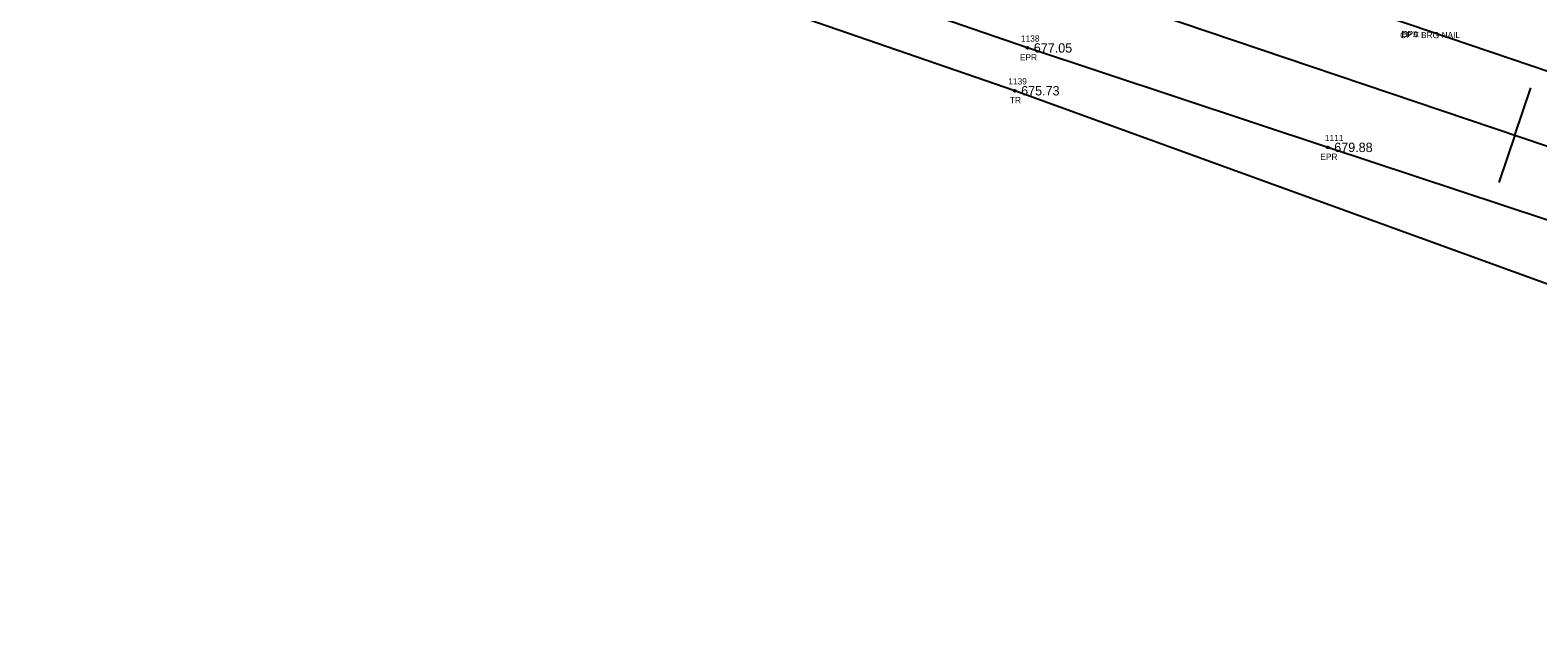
# Model space of a CAD drawing. Extents: x 1655137 to 1657928, y 1003994 to 1005407.
# Drawn here: x 1656606.1 to 1656847.1, y 1004388.9 to 1004485.2 of the extents above; entities that cross this region are included whole.
import ezdxf

# ---------------------------------------------------------------- set-up
doc = ezdxf.new("R2010")
doc.units = 0
for name, color, linetype in [('RD_EX_Driveway_txCode', 7, 'Continuous'), ('RD_EX_Road', 7, 'Continuous'), ('RD_EX_Road_txCode', 7, 'Continuous'), ('RD_EX_TX_Road_ELEV', 7, 'Continuous'), ('RD_EX_TX_VEG_ELEV', 7, 'Continuous'), ('RD_EX_VEG', 7, 'Continuous'), ('RD_EX_VEG_txCode', 7, 'Continuous'), ('RD_HC_Cl', 7, 'Continuous'), ('RD_HC_Data_Tic', 7, 'Continuous'), ('RD_HC_Survey_txCode', 7, 'Continuous'), ('RD_SMD_Locator', 7, 'Continuous')]:
    doc.layers.add(name, color=color, linetype=linetype)

msp = doc.modelspace()

# ---------------------------------------------------------------- linework, layer by layer
at = {"layer": 'RD_EX_Road'}
for points in [[(1657064.39, 1004409.09), (1657015.67, 1004424.64), (1656965.82, 1004440.6), (1656917.99, 1004455.95), (1656868.5, 1004471.86), (1656826.53, 1004486.06), (1656801.74, 1004494.51), (1656772.14, 1004504.27), (1656723.45, 1004520.92), (1656674.94, 1004537.34), (1656626.5, 1004553.88), (1656578.27, 1004569.52), (1656529.18, 1004584.75), (1656481.5, 1004600.51), (1656432.67, 1004617.14), (1656404.34, 1004625.82)], [(1657057.77, 1004388.92), (1657009.7, 1004404.08), (1656958.18, 1004419.84), (1656956.49, 1004419.67), (1656924.83, 1004429.55), (1656916.51, 1004432.8), (1656911.19, 1004434.68), (1656862.46, 1004450.21), (1656813.53, 1004466.42), (1656765.51, 1004482.33), (1656716.81, 1004499.14), (1656668.6, 1004515.93), (1656620.24, 1004532.54), (1656571.72, 1004548.37), (1656523.3, 1004563.77), (1656474.37, 1004580.29), (1656426.43, 1004596.82), (1656398.22, 1004606.78)]]:
    msp.add_lwpolyline(points, dxfattribs=at)
at = {"layer": 'RD_EX_VEG'}
msp.add_lwpolyline([(1656891.08, 1004405.37), (1656915.13, 1004420.4), (1656763.49, 1004475.48), (1656570, 1004542.2), (1656467.82, 1004565.09), (1656367.55, 1004594.62), (1656280.9, 1004634.63), (1656273.57, 1004608.65)], dxfattribs=at)
at = {"layer": 'RD_HC_Cl'}
msp.add_line((1656624.52, 1004542.44), (1656857.94, 1004463.43), dxfattribs=at)
at = {"layer": 'RD_HC_Data_Tic'}
for q in [(1656845.95, 1004475.93), (1656840.82, 1004460.78)]:
    msp.add_line((1656843.38, 1004468.36), q, dxfattribs=at)
at = {"layer": 'RD_SMD_Locator'}
for centre in [(1656765.51, 1004482.33), (1656763.49, 1004475.48), (1656813.53, 1004466.42)]:
    msp.add_circle(centre, 0.15, dxfattribs=at)

# ---------------------------------------------------------------- texts
at = {"layer": 'RD_EX_Driveway_txCode'}
msp.add_text('DPA', height=1, dxfattribs=at).set_placement((1656825.27, 1004484.06))
at = {"layer": 'RD_EX_Road_txCode'}
for s, p in [('1138', (1656764.45, 1004483.33)), ('EPL', (1656825.33, 1004484.06)), ('EPR', (1656764.28, 1004480.33)), ('1111', (1656813.03, 1004467.42)), ('EPR', (1656812.3, 1004464.42))]:
    msp.add_text(s, height=1, dxfattribs=at).set_placement(p)
at = {"layer": 'RD_EX_TX_Road_ELEV'}
for s, p in [('677.05', (1656766.51, 1004481.58)), ('679.88', (1656814.53, 1004465.67))]:
    msp.add_text(s, height=1.5, dxfattribs=at).set_placement(p)
at = {"layer": 'RD_EX_TX_VEG_ELEV'}
msp.add_text('675.73', height=1.5, dxfattribs=at).set_placement((1656764.49, 1004474.73))
at = {"layer": 'RD_EX_VEG_txCode'}
for s, p in [('1139', (1656762.43, 1004476.48)), ('TR', (1656762.69, 1004473.48))]:
    msp.add_text(s, height=1, dxfattribs=at).set_placement(p)
at = {"layer": 'RD_HC_Survey_txCode'}
msp.add_text('CP 7 BRG NAIL', height=1, dxfattribs=at).set_placement((1656825.06, 1004483.89))

doc.saveas('drawing.dxf')
